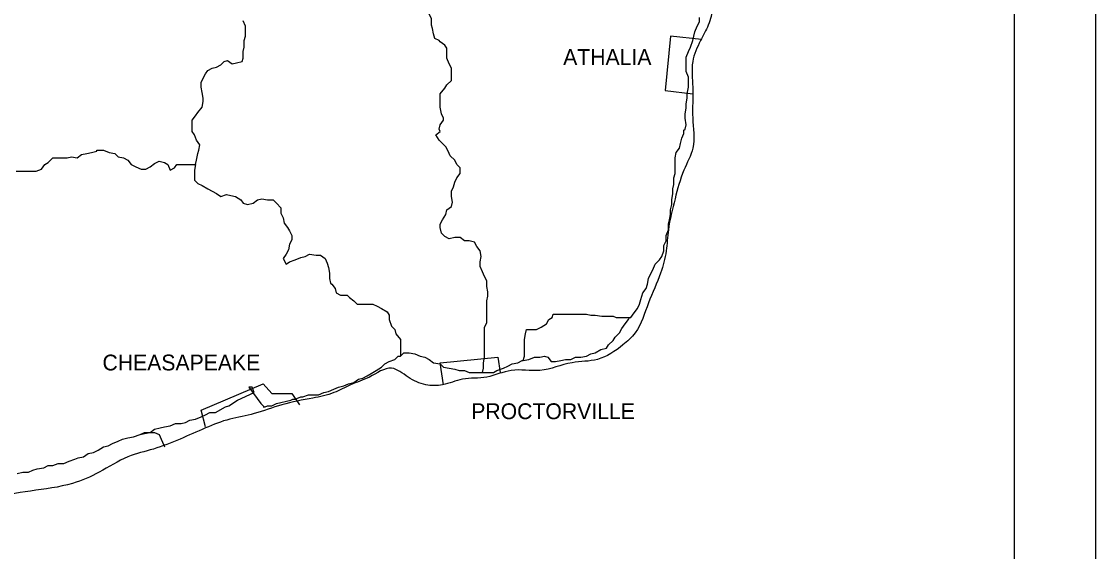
# Model space of a CAD drawing. Extents: x 0 to 34, y 0 to 22.
# Drawn here: x 7.678 to 9, y 14.798 to 15.451 of the extents above; entities that cross this region are included whole.
import ezdxf

# ---------------------------------------------------------------- set-up
doc = ezdxf.new("R2010")
doc.units = 0
doc.layers.add('Default', color=7, linetype='Continuous')
doc.layers.add('SH_Data', color=7, linetype='Continuous')

msp = doc.modelspace()

# ---------------------------------------------------------------- linework, layer by layer
at = {"layer": 'Default'}
for points in [[(8.1919, 15.427), (8.1864, 15.4297), (8.1851, 15.4352), (8.1837, 15.442), (8.1824, 15.4461), (8.1824, 15.4543), (8.1796, 15.4597), (8.1796, 15.4665), (8.1851, 15.4706), (8.1905, 15.4747), (8.1946, 15.4788), (8.1974, 15.4843), (8.1933, 15.4897), (8.1905, 15.4952), (8.1878, 15.5006), (8.1878, 15.5074), (8.1878, 15.5088), (8.1878, 15.5102)], [(7.9274, 15.4011), (7.9315, 15.4025), (7.9369, 15.3984), (7.9424, 15.3997), (7.9492, 15.4011), (7.9506, 15.4052), (7.9506, 15.4134), (7.9519, 15.4188), (7.9519, 15.427), (7.9533, 15.4324), (7.9533, 15.4393), (7.9533, 15.4447), (7.9506, 15.4515)], [(8.4946, 15.3179), (8.4959, 15.3234), (8.4946, 15.3316), (8.4946, 15.337), (8.4959, 15.3438), (8.4959, 15.3493), (8.4973, 15.3561), (8.4973, 15.3616), (8.4987, 15.3697), (8.4987, 15.3752), (8.4987, 15.382), (8.4959, 15.3888), (8.4959, 15.3943), (8.4959, 15.4011), (8.4959, 15.4065), (8.4987, 15.4134), (8.5014, 15.4188), (8.5041, 15.427), (8.5055, 15.4324), (8.5068, 15.4379), (8.5096, 15.4447), (8.5123, 15.4502), (8.5123, 15.4556)], [(8.515, 15.4284), (8.4769, 15.4324), (8.47, 15.3656), (8.5041, 15.3616)], [(8.2069, 15.3861), (8.2069, 15.3929), (8.2042, 15.3984), (8.2014, 15.4052), (8.2014, 15.4106), (8.2014, 15.4175), (8.1987, 15.4215), (8.1933, 15.4256), (8.1919, 15.427)], [(7.9069, 15.3902), (7.9124, 15.3929), (7.9178, 15.3943), (7.9233, 15.397), (7.9274, 15.4011)], [(7.9069, 15.3902), (7.9124, 15.3929), (7.9178, 15.3943), (7.9233, 15.397), (7.9274, 15.4011)], [(7.8919, 15.2743), (7.8933, 15.2797), (7.8947, 15.2879), (7.896, 15.292), (7.8974, 15.2988), (7.8933, 15.3043), (7.8906, 15.3111), (7.8879, 15.3152), (7.8879, 15.3234), (7.8879, 15.3288), (7.8919, 15.3343), (7.8947, 15.3384), (7.9001, 15.3452), (7.9015, 15.352), (7.9015, 15.3561), (7.9001, 15.3629), (7.8988, 15.3697), (7.8988, 15.3752), (7.9015, 15.3806), (7.9042, 15.3861), (7.9069, 15.3902), (7.9069, 15.3902)], [(8.1974, 15.3316), (8.1946, 15.337), (8.1933, 15.3452), (8.1933, 15.3506), (8.1933, 15.3561), (8.1933, 15.3616), (8.1987, 15.3684), (8.2014, 15.3725), (8.2069, 15.3779), (8.2069, 15.3847), (8.2069, 15.3861)], [(8.1933, 15.2007), (8.196, 15.2061), (8.2001, 15.2129), (8.2014, 15.2184), (8.2069, 15.2225), (8.2083, 15.2279), (8.2069, 15.2348), (8.2069, 15.2416), (8.2096, 15.247), (8.211, 15.2525), (8.2137, 15.2579), (8.2178, 15.2634), (8.2178, 15.2702), (8.2137, 15.2743), (8.211, 15.2797), (8.2055, 15.2852), (8.2028, 15.2907), (8.2001, 15.2961), (8.196, 15.3002), (8.1919, 15.3043), (8.1878, 15.3111), (8.1933, 15.3152), (8.1919, 15.3179), (8.1933, 15.3234), (8.1974, 15.3288), (8.1974, 15.3316), (8.1974, 15.3316), (8.1974, 15.3316)], [(8.4278, 15.0861), (8.4319, 15.0916), (8.4359, 15.097), (8.4387, 15.1025), (8.44, 15.108), (8.4428, 15.1161), (8.4469, 15.1216), (8.4482, 15.127), (8.4496, 15.1339), (8.4523, 15.1393), (8.455, 15.1448), (8.4578, 15.1516), (8.4632, 15.157), (8.4659, 15.1611), (8.4687, 15.1679), (8.4687, 15.1748), (8.4714, 15.1802), (8.4714, 15.187), (8.4741, 15.1938), (8.4741, 15.2007), (8.4755, 15.2061), (8.4769, 15.2129), (8.4769, 15.2184), (8.4782, 15.2252), (8.4782, 15.2307), (8.4796, 15.2388), (8.4796, 15.2443), (8.4809, 15.2497), (8.4809, 15.2579), (8.4823, 15.2634), (8.4823, 15.2702), (8.4823, 15.2757), (8.4823, 15.2825), (8.4837, 15.2893), (8.4878, 15.2947), (8.4891, 15.3002), (8.4905, 15.307), (8.4932, 15.3125), (8.4932, 15.3166), (8.4946, 15.3179)], [(7.6711, 15.2661), (7.6779, 15.2661), (7.6833, 15.2661), (7.6888, 15.2661), (7.6956, 15.2661), (7.7024, 15.2688), (7.7065, 15.2743), (7.7106, 15.277), (7.7161, 15.2825), (7.7202, 15.2825), (7.727, 15.2825), (7.7338, 15.2825), (7.7392, 15.2838), (7.7461, 15.2825), (7.7515, 15.2866), (7.7583, 15.2879), (7.7638, 15.2893), (7.7706, 15.2907), (7.7706, 15.292), (7.7747, 15.292)], [(7.7747, 15.292), (7.7788, 15.292), (7.7856, 15.2893), (7.7924, 15.2879), (7.7965, 15.2838), (7.8033, 15.2825), (7.8088, 15.2797), (7.8129, 15.2743), (7.8183, 15.2716), (7.8251, 15.2688), (7.8306, 15.2688), (7.836, 15.2716), (7.8415, 15.2757), (7.847, 15.2784), (7.8538, 15.277), (7.8579, 15.2743), (7.8606, 15.2675), (7.866, 15.2702), (7.8688, 15.2743), (7.8756, 15.2743), (7.8824, 15.2743), (7.8879, 15.2743), (7.8919, 15.2743)], [(7.8919, 15.2743), (7.8906, 15.2675), (7.8906, 15.262), (7.8906, 15.2552), (7.8947, 15.2511), (7.9001, 15.2484), (7.9069, 15.2443), (7.9124, 15.2416), (7.9178, 15.2388), (7.9233, 15.2348), (7.9301, 15.2375), (7.9356, 15.2361), (7.941, 15.2348), (7.9478, 15.2307)], [(7.9478, 15.2307), (7.9506, 15.2266), (7.956, 15.2252), (7.9628, 15.2266), (7.9683, 15.2307), (7.9737, 15.232), (7.9806, 15.2307), (7.9874, 15.2307), (7.9915, 15.2266), (7.9969, 15.2211), (7.9969, 15.2143), (7.9997, 15.2088), (8.001, 15.202), (8.0051, 15.1966), (8.0078, 15.1925), (8.0106, 15.187), (8.0106, 15.1816), (8.0078, 15.1761), (8.0065, 15.1693), (8.0037, 15.1639), (7.9997, 15.1584), (8.0037, 15.1516), (8.0078, 15.1543), (8.0147, 15.157), (8.0215, 15.1598), (8.0269, 15.1611), (8.0324, 15.1639), (8.0406, 15.1625), (8.046, 15.1625), (8.0515, 15.1584), (8.0542, 15.1529), (8.0556, 15.1475), (8.0569, 15.1407), (8.0569, 15.1339), (8.0583, 15.1284), (8.0596, 15.127)], [(8.2519, 15.1175), (8.2505, 15.1243), (8.2505, 15.1311), (8.2478, 15.1366), (8.2451, 15.142), (8.2423, 15.1489), (8.2423, 15.1543), (8.2437, 15.1611), (8.2423, 15.1679), (8.2383, 15.1734), (8.2355, 15.1789), (8.2287, 15.1802), (8.2233, 15.1802), (8.2178, 15.1843), (8.211, 15.1843), (8.2042, 15.1829), (8.1987, 15.1857), (8.1946, 15.1898), (8.1933, 15.1966), (8.1933, 15.2007)], [(8.0596, 15.127), (8.0637, 15.1216), (8.0651, 15.1161), (8.0706, 15.1134), (8.0787, 15.1134), (8.0815, 15.1107), (8.0869, 15.1066), (8.091, 15.1025), (8.0978, 15.1025), (8.1046, 15.1025), (8.1101, 15.1025), (8.1155, 15.0998), (8.121, 15.097), (8.1278, 15.093), (8.1305, 15.0889), (8.1305, 15.0834), (8.1333, 15.0752), (8.1374, 15.0711), (8.1387, 15.0657), (8.1442, 15.0589), (8.1442, 15.0534), (8.1442, 15.048), (8.1442, 15.0411), (8.1442, 15.0384)], [(8.2451, 15.018), (8.2464, 15.0234), (8.2464, 15.0302), (8.2478, 15.0371), (8.2478, 15.0425), (8.2478, 15.0493), (8.2478, 15.0548), (8.2478, 15.0616), (8.2478, 15.0698), (8.2478, 15.0739), (8.2505, 15.0793), (8.2505, 15.0861), (8.2505, 15.093), (8.2505, 15.0998), (8.2505, 15.1066), (8.2519, 15.112), (8.2519, 15.1161), (8.2519, 15.1175)], [(8.2955, 15.033), (8.2969, 15.0384), (8.2969, 15.0466), (8.2969, 15.0534), (8.2969, 15.0589), (8.2982, 15.0657), (8.2996, 15.0711), (8.3051, 15.0711), (8.3119, 15.0711), (8.3173, 15.0739), (8.3241, 15.078), (8.3269, 15.0834), (8.331, 15.0861), (8.3323, 15.0902), (8.3337, 15.0902)], [(8.3337, 15.0902), (8.3405, 15.0902), (8.346, 15.0902), (8.3528, 15.0902), (8.3596, 15.0902), (8.3664, 15.0902), (8.3732, 15.0902), (8.3787, 15.0889), (8.3841, 15.0889), (8.3923, 15.0875), (8.3978, 15.0875), (8.406, 15.0875), (8.41, 15.0861), (8.4182, 15.0861), (8.4278, 15.0861)], [(8.2955, 15.033), (8.3023, 15.0343), (8.3092, 15.0371), (8.316, 15.0371), (8.3214, 15.0384), (8.3255, 15.0371), (8.3296, 15.0316), (8.3351, 15.0316), (8.3419, 15.033), (8.3473, 15.0343), (8.3541, 15.0343), (8.3596, 15.0371), (8.3664, 15.0371), (8.3732, 15.0384), (8.3787, 15.0411), (8.3841, 15.0425), (8.391, 15.0466), (8.3978, 15.048), (8.4005, 15.0521), (8.406, 15.0575), (8.4087, 15.0616), (8.4141, 15.0671), (8.4169, 15.0725), (8.421, 15.078), (8.425, 15.0834), (8.4264, 15.0861), (8.4278, 15.0861)], [(7.9778, 14.9757), (7.9806, 14.9771), (7.986, 14.9771), (7.9915, 14.9798), (8.0092, 14.9839), (8.0119, 14.9852), (8.0147, 14.9852), (8.0215, 14.988), (8.0242, 14.988), (8.031, 14.9907), (8.0378, 14.9907), (8.0433, 14.9907), (8.0501, 14.9934), (8.0556, 14.9948), (8.0624, 14.9975), (8.0678, 15.0002), (8.0746, 15.0016), (8.0801, 15.0043), (8.0869, 15.0057), (8.0924, 15.0098), (8.0978, 15.0112), (8.1033, 15.0139), (8.1101, 15.018), (8.1142, 15.0207), (8.121, 15.0248), (8.1251, 15.0289), (8.1305, 15.0316), (8.1374, 15.0343), (8.1415, 15.0384), (8.1428, 15.0384), (8.1442, 15.0384)], [(8.1442, 15.0384), (8.1483, 15.0425), (8.1551, 15.0425), (8.1619, 15.0411), (8.1687, 15.0384), (8.1742, 15.0371), (8.1796, 15.0343), (8.1851, 15.0302), (8.1933, 15.0289), (8.1974, 15.0248), (8.2042, 15.0234), (8.211, 15.0221), (8.2164, 15.0207), (8.2233, 15.0207), (8.2287, 15.018), (8.2355, 15.018), (8.2423, 15.018), (8.2451, 15.018), (8.2451, 15.018)], [(8.1442, 15.0384), (8.1483, 15.0425), (8.1551, 15.0425), (8.1619, 15.0411), (8.1687, 15.0384), (8.1742, 15.0371), (8.1796, 15.0343), (8.1851, 15.0302), (8.1933, 15.0289), (8.1974, 15.0248), (8.2042, 15.0234), (8.211, 15.0221), (8.2164, 15.0207), (8.2233, 15.0207), (8.2287, 15.018), (8.2355, 15.018), (8.2423, 15.018), (8.2451, 15.018), (8.2451, 15.018)], [(8.1974, 15.003), (8.1933, 15.0302), (8.2642, 15.0371), (8.2669, 15.018)], [(8.2451, 15.018), (8.2533, 15.018), (8.2587, 15.018), (8.2628, 15.0207), (8.271, 15.0234), (8.2764, 15.0261), (8.2819, 15.0289), (8.2887, 15.0302), (8.2942, 15.033), (8.2955, 15.033)], [(8.2451, 15.018), (8.2533, 15.018), (8.2587, 15.018), (8.2628, 15.0207), (8.271, 15.0234), (8.2764, 15.0261), (8.2819, 15.0289), (8.2887, 15.0302), (8.2942, 15.033), (8.2955, 15.033)], [(7.8238, 14.9416), (7.8292, 14.9443), (7.836, 14.9443), (7.8415, 14.9484), (7.8483, 14.9498), (7.8538, 14.9512), (7.8606, 14.9525), (7.8674, 14.9553), (7.8742, 14.9553), (7.8797, 14.9566), (7.8851, 14.9593), (7.8919, 14.9607), (7.8988, 14.9634), (7.9042, 14.9662), (7.9097, 14.9689), (7.9165, 14.9689), (7.9288, 14.9757), (7.9328, 14.9771), (7.9438, 14.9839), (7.9642, 14.9934), (7.9615, 15.0002), (7.9574, 15.0002), (7.9724, 14.9798), (7.9751, 14.9771), (7.9765, 14.9757), (7.9765, 14.9757), (7.9751, 14.9757), (7.9778, 14.9757)], [(7.9042, 14.9512), (7.8988, 14.9716), (7.9751, 15.0043), (7.986, 14.9921), (8.0106, 14.9921), (8.0201, 14.9784)], [(7.8238, 14.9416), (7.8292, 14.943), (7.836, 14.9443), (7.8415, 14.9443), (7.847, 14.9416), (7.8538, 14.9266), (7.8538, 14.9266)], [(7.6724, 14.8939), (7.6793, 14.8953), (7.6861, 14.8953), (7.6915, 14.898), (7.697, 14.8994), (7.7052, 14.9007), (7.7106, 14.9034), (7.7161, 14.9034), (7.7229, 14.9062), (7.7297, 14.9062), (7.7365, 14.9089), (7.7433, 14.9116), (7.7474, 14.913), (7.7542, 14.9143), (7.7597, 14.9184), (7.7665, 14.9198), (7.772, 14.9225), (7.7788, 14.9266), (7.7842, 14.928), (7.7897, 14.9307), (7.7965, 14.9334), (7.802, 14.9362), (7.8088, 14.9375), (7.8156, 14.9389), (7.8238, 14.9416)]]:
    msp.add_lwpolyline(points, dxfattribs=at)
msp.add_spline([(8.5655, 15.6738), (8.545, 15.6479), (8.5382, 15.6233), (8.545, 15.5852), (8.5382, 15.5702), (8.5355, 15.5429), (8.5287, 15.517), (8.5287, 15.4965), (8.5287, 15.4679), (8.5232, 15.4461), (8.5137, 15.427), (8.5041, 15.4011), (8.5041, 15.3697), (8.5041, 15.3316), (8.5041, 15.2947), (8.4932, 15.2675), (8.4823, 15.232), (8.4741, 15.1938), (8.4714, 15.1679), (8.4646, 15.1407), (8.4496, 15.1039), (8.4332, 15.0671), (8.4182, 15.0521), (8.3869, 15.0343), (8.3555, 15.0302), (8.316, 15.0207), (8.2805, 15.0207), (8.2505, 15.0125), (8.2205, 15.0098), (8.196, 15.003), (8.1755, 15.003), (8.1537, 15.0125), (8.1333, 15.0234), (8.106, 15.0125), (8.0828, 15.003), (8.0624, 14.9934), (8.0365, 14.9866), (7.9983, 14.9784), (7.9642, 14.9675), (7.9342, 14.9607), (7.9042, 14.9498), (7.8729, 14.9362), (7.8401, 14.9239), (7.8088, 14.9143), (7.7733, 14.8953), (7.7406, 14.8816), (7.6888, 14.8721), (7.637, 14.8653), (7.5961, 14.8653), (7.5552, 14.8721), (7.5184, 14.8871), (7.4911, 14.9143), (7.4706, 14.928), (7.457, 14.9607), (7.4488, 14.988), (7.4434, 15.0302), (7.4434, 15.0548), (7.4338, 15.0943), (7.4338, 15.1161), (7.4243, 15.1366), (7.4134, 15.1789), (7.382, 15.1898), (7.3643, 15.2034), (7.3207, 15.232), (7.2866, 15.2457), (7.2539, 15.2743), (7.2266, 15.3166), (7.1911, 15.352), (7.1625, 15.3943), (7.1489, 15.4338), (7.1271, 15.4761), (7.0889, 15.4965), (7.0643, 15.5211), (7.033, 15.5429), (7.0044, 15.5592), (6.9798, 15.5702), (6.9294, 15.5702), (6.898, 15.5702), (6.8762, 15.5742), (6.8448, 15.5702), (6.8244, 15.5702), (6.7808, 15.5742), (6.7385, 15.5852), (6.7153, 15.6056), (6.6853, 15.6179)], degree=3, dxfattribs=at)
at = {"layer": 'SH_Data'}
for p, q in [((9, 21), (9, 14)), ((8.9, 20.9), (8.9, 14.1))]:
    msp.add_line(p, q, dxfattribs=at)

# ---------------------------------------------------------------- texts
at = {"layer": 'Default'}
for s, height, p in [('ATHALIA', 0.0195, (8.3446, 15.397)), ('CHEASAPEAKE', 0.019502, (7.7774, 15.0207)), ('PROCTORVILLE', 0.019502, (8.2314, 14.9607))]:
    msp.add_text(s, height=height, dxfattribs=at).set_placement(p)

doc.saveas('drawing.dxf')
